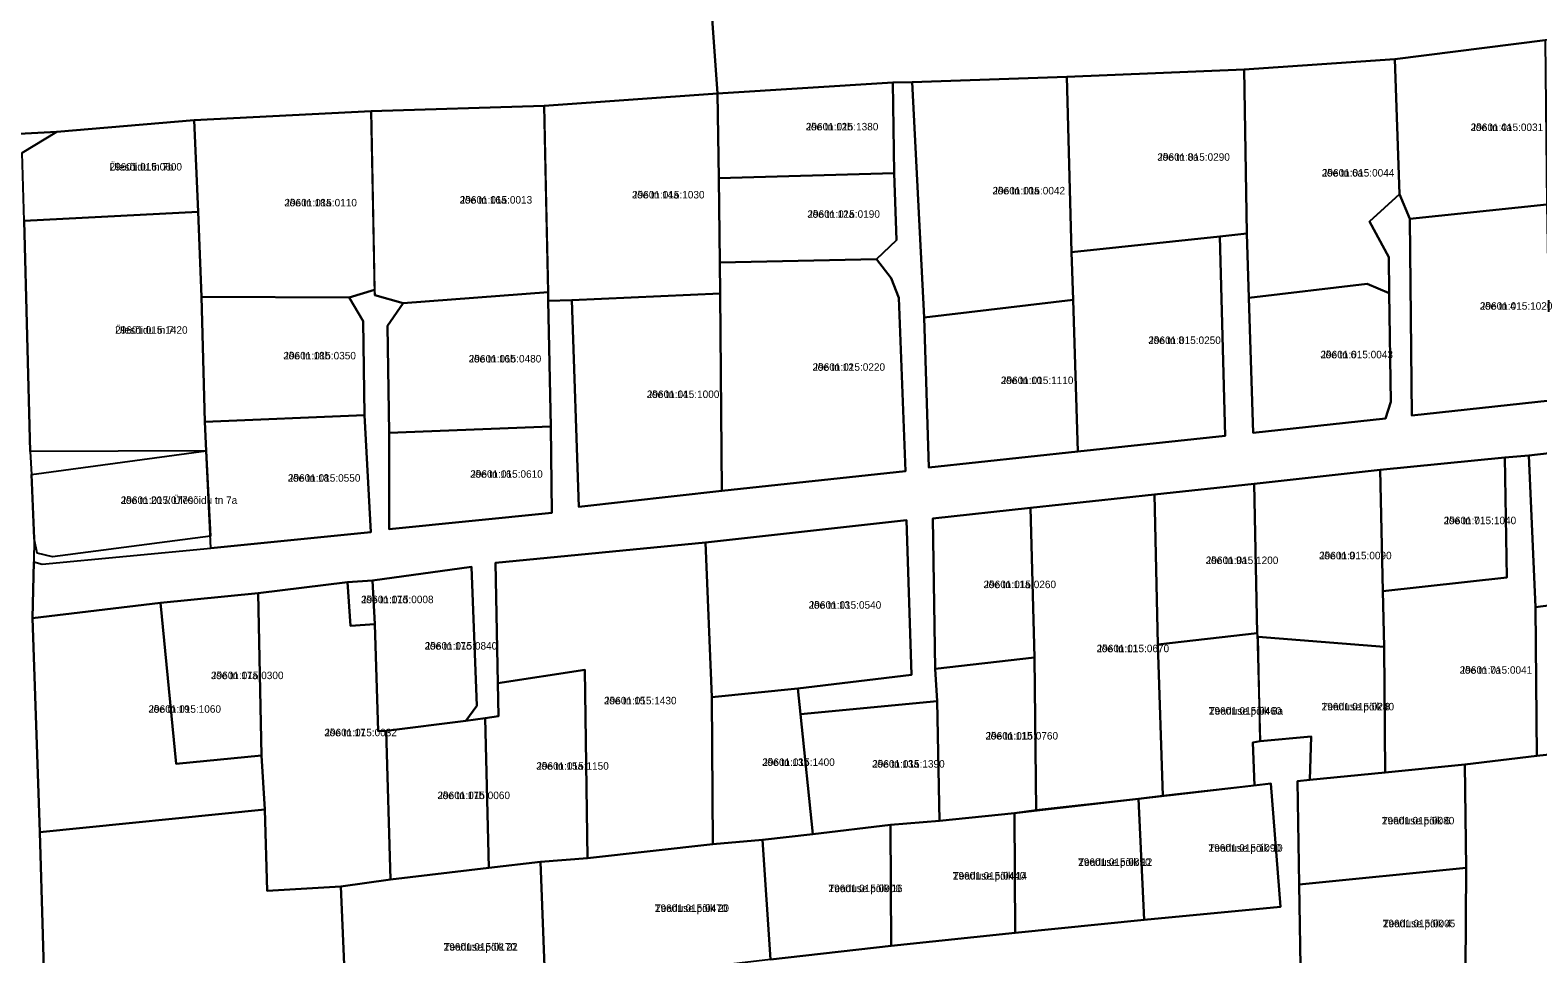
# Model space of a CAD drawing. Extents: x 518839 to 525192, y 6573164 to 6576561.
# Drawn here: x 524240.2 to 524541.9, y 6574114.7 to 6574299.5 of the extents above; entities that cross this region are included whole.
import ezdxf

# ---------------------------------------------------------------- set-up
doc = ezdxf.new("R2010")
doc.units = 0
for name, color, linetype in [('L_AADRESS', 7, 'Continuous'), ('PIIR', 7, 'Continuous'), ('TUNNUS', 7, 'Continuous')]:
    doc.layers.add(name, color=color, linetype=linetype)

msp = doc.modelspace()

# ---------------------------------------------------------------- linework, layer by layer
at = {"layer": 'PIIR'}
for points in [[(524374.42, 6574333.78), (524377.78, 6574286.88), (524343.06, 6574284.39), (524308.48, 6574283.33), (524273.05, 6574281.52), (524245.54, 6574279.22), (524236.65, 6574278.75)], [(524603.25, 6574305.18), (524560.4, 6574299.4), (524543.42, 6574297.51), (524513.3, 6574293.76), (524483.18, 6574291.7), (524447.68, 6574290.19), (524416.73, 6574289.11), (524412.88, 6574289.05), (524377.78, 6574286.88), (524374.42, 6574333.78)], [(524569.73, 6574217.81), (524540.13, 6574214.39), (524535.35, 6574214.04), (524510.4, 6574211.51), (524485.18, 6574208.72), (524465.23, 6574206.58), (524440.39, 6574203.91), (524420.86, 6574201.78), (524421.31, 6574171.7), (524421.74, 6574165.24), (524394.36, 6574162.67), (524393.82, 6574167.78), (524416.62, 6574170.5), (524415.6, 6574201.48), (524375.36, 6574196.98), (524333.35, 6574192.94), (524333.78, 6574168.84), (524333.97, 6574162.26), (524331.28, 6574161.82), (524327.38, 6574161.32), (524329.62, 6574164.28), (524328.56, 6574192.15), (524308.74, 6574189.42), (524303.69, 6574189.04), (524285.84, 6574186.87), (524266.3, 6574184.93), (524240.65, 6574181.86), (524240.91, 6574193.14), (524242.63, 6574192.69), (524276.39, 6574195.86), (524308.41, 6574199.08), (524307.1, 6574222.48), (524306.85, 6574241.32), (524304.03, 6574246.04), (524309.15, 6574247.55), (524309.17, 6574246.47), (524314.87, 6574244.93), (524311.74, 6574240.35), (524312.04, 6574218.94), (524312.08, 6574199.69), (524344.61, 6574202.92), (524344.41, 6574220.23), (524343.91, 6574245.35), (524348.63, 6574245.53), (524350.02, 6574204.11), (524378.65, 6574207.36), (524415.39, 6574211.28), (524414.07, 6574245.95), (524412.52, 6574249.93), (524409.62, 6574253.72), (524413.56, 6574257.48), (524413.15, 6574270.95), (524412.88, 6574289.05), (524416.73, 6574289.11), (524419.11, 6574242.02), (524420.07, 6574211.99), (524449.9, 6574215.23), (524479.4, 6574218.33), (524478.3, 6574258.27), (524483.73, 6574258.85), (524484.12, 6574245.98), (524484.94, 6574218.93), (524511.47, 6574221.81), (524512.54, 6574225.12), (524512.22, 6574246.88), (524512.12, 6574254.09), (524508.28, 6574261.23), (524514.29, 6574266.69), (524516.32, 6574261.81), (524516.72, 6574222.41), (524544.4, 6574225.45)], [(524236.65, 6574278.75), (524245.54, 6574279.22), (524238.6, 6574275.01)], [(524238.98, 6574261.37), (524240.23, 6574215.18), (524240.48, 6574210.62), (524241.02, 6574197.83), (524240.91, 6574193.14), (524240.65, 6574181.86), (524242.13, 6574138.99), (524243.35, 6574097.92), (524243.96, 6574077.71), (524245.35, 6574041.84), (524245.17, 6574032.64), (524245.98, 6574004.81), (524246.26, 6573990.17), (524246.35, 6573972.48), (524246.84, 6573953.26), (524247.54, 6573920.4), (524247.28, 6573908.17), (524248.4, 6573876.78), (524250.25, 6573836.78)], [(524388.38, 6574113.52), (524412.54, 6574116.25), (524437.36, 6574118.89), (524463.13, 6574121.46), (524490.46, 6574124.08), (524488.49, 6574148.75), (524485.27, 6574148.38), (524484.92, 6574156.99), (524486.37, 6574157.21), (524496.58, 6574158.19), (524496.29, 6574149.47), (524493.82, 6574149.22), (524494.16, 6574128.57), (524494.48, 6574108.1)]]:
    msp.add_lwpolyline(points, dxfattribs=at)
for points in [[(524513.3, 6574293.76), (524543.42, 6574297.51), (524543.72, 6574264.65), (524516.32, 6574261.81), (524514.29, 6574266.69)], [(524483.18, 6574291.7), (524513.3, 6574293.76), (524514.29, 6574266.69), (524508.28, 6574261.23), (524512.12, 6574254.09), (524512.22, 6574246.88), (524507.77, 6574248.8), (524484.12, 6574245.98), (524483.73, 6574258.85)], [(524416.73, 6574289.11), (524447.68, 6574290.19), (524448.61, 6574255.1), (524448.92, 6574245.6), (524419.11, 6574242.02)], [(524447.68, 6574290.19), (524483.18, 6574291.7), (524483.73, 6574258.85), (524478.3, 6574258.27), (524448.61, 6574255.1)], [(524377.78, 6574286.88), (524412.88, 6574289.05), (524413.15, 6574270.95), (524378.03, 6574269.9)], [(524343.48, 6574264.51), (524343.88, 6574247.11), (524314.87, 6574244.93), (524309.17, 6574246.47), (524308.85, 6574263.82), (524308.48, 6574283.33), (524343.06, 6574284.39)], [(524377.78, 6574286.88), (524378.03, 6574269.9), (524378.21, 6574253.02), (524378.27, 6574246.84), (524348.63, 6574245.53), (524343.91, 6574245.35), (524343.88, 6574247.11), (524343.06, 6574284.39)], [(524273.82, 6574263.18), (524238.98, 6574261.37), (524238.6, 6574275.01), (524245.54, 6574279.22), (524273.05, 6574281.52)], [(524273.82, 6574263.18), (524273.05, 6574281.52), (524308.48, 6574283.33), (524309.15, 6574247.55), (524304.03, 6574246.04), (524274.53, 6574246.16)], [(524378.03, 6574269.9), (524413.15, 6574270.95), (524413.56, 6574257.48), (524409.62, 6574253.72), (524378.21, 6574253.02)], [(524273.82, 6574263.18), (524274.53, 6574246.16), (524275.17, 6574221.13), (524275.45, 6574215.33), (524240.23, 6574215.18), (524238.98, 6574261.37)], [(524516.32, 6574261.81), (524543.72, 6574264.65), (524544.4, 6574225.45), (524516.72, 6574222.41)], [(524448.92, 6574245.6), (524448.61, 6574255.1), (524478.3, 6574258.27), (524479.4, 6574218.33), (524449.9, 6574215.23)], [(524378.27, 6574246.84), (524378.21, 6574253.02), (524409.62, 6574253.72), (524412.52, 6574249.93), (524414.07, 6574245.95), (524415.39, 6574211.28), (524378.65, 6574207.36)], [(524484.12, 6574245.98), (524507.77, 6574248.8), (524512.22, 6574246.88), (524512.54, 6574225.12), (524511.47, 6574221.81), (524484.94, 6574218.93)], [(524274.53, 6574246.16), (524304.03, 6574246.04), (524306.85, 6574241.32), (524307.1, 6574222.48), (524275.17, 6574221.13)], [(524311.74, 6574240.35), (524314.87, 6574244.93), (524343.88, 6574247.11), (524343.91, 6574245.35), (524344.41, 6574220.23), (524312.04, 6574218.94)], [(524348.63, 6574245.53), (524378.27, 6574246.84), (524378.65, 6574207.36), (524350.02, 6574204.11)], [(524419.11, 6574242.02), (524448.92, 6574245.6), (524449.9, 6574215.23), (524420.07, 6574211.99)], [(524275.45, 6574215.33), (524275.17, 6574221.13), (524307.1, 6574222.48), (524308.41, 6574199.08), (524276.39, 6574195.86)], [(524312.04, 6574218.94), (524344.41, 6574220.23), (524344.61, 6574202.92), (524312.08, 6574199.69)], [(524569.73, 6574217.81), (524569.35, 6574187.66), (524541.45, 6574184.05), (524540.13, 6574214.39)], [(524240.48, 6574210.62), (524275.45, 6574215.33), (524276.27, 6574198.28), (524244.71, 6574194.11), (524241.62, 6574194.83), (524241.02, 6574197.83)], [(524510.4, 6574211.51), (524535.35, 6574214.04), (524535.77, 6574189.99), (524510.93, 6574187.29)], [(524535.35, 6574214.04), (524540.13, 6574214.39), (524541.45, 6574184.05), (524541.71, 6574154.3), (524527.33, 6574152.59), (524511.39, 6574150.99), (524511.18, 6574176.09), (524510.93, 6574187.29), (524535.77, 6574189.99)], [(524485.18, 6574208.72), (524485.8, 6574178.88), (524465.86, 6574176.59), (524465.23, 6574206.58)], [(524485.8, 6574178.88), (524485.18, 6574208.72), (524510.4, 6574211.51), (524510.93, 6574187.29), (524511.18, 6574176.09), (524485.95, 6574178.09)], [(524466.91, 6574146.26), (524462.01, 6574145.66), (524441.53, 6574143.44), (524441.19, 6574174), (524440.39, 6574203.91), (524465.23, 6574206.58), (524465.86, 6574176.59)], [(524420.86, 6574201.78), (524440.39, 6574203.91), (524441.19, 6574174), (524421.31, 6574171.7)], [(524415.6, 6574201.48), (524416.62, 6574170.5), (524393.82, 6574167.78), (524376.6, 6574166.02), (524375.36, 6574196.98)], [(524351.2, 6574171.53), (524333.78, 6574168.84), (524333.35, 6574192.94), (524375.36, 6574196.98), (524376.6, 6574166.02), (524376.8, 6574136.64), (524351.74, 6574133.81)], [(524328.56, 6574192.15), (524329.62, 6574164.28), (524327.38, 6574161.32), (524311.47, 6574159.28), (524309.86, 6574159.26), (524309.19, 6574180.62), (524308.74, 6574189.42)], [(524285.84, 6574186.87), (524303.69, 6574189.04), (524304.33, 6574180.33), (524309.19, 6574180.62), (524309.86, 6574159.26), (524311.47, 6574159.28), (524312.35, 6574129.57), (524302.37, 6574128.15), (524287.66, 6574127.29), (524287.15, 6574143.56), (524286.53, 6574154.38)], [(524308.74, 6574189.42), (524309.19, 6574180.62), (524304.33, 6574180.33), (524303.69, 6574189.04)], [(524569.35, 6574187.66), (524571.4, 6574178.17), (524571.46, 6574157.47), (524566.75, 6574156.97), (524541.71, 6574154.3), (524541.45, 6574184.05)], [(524240.65, 6574181.86), (524266.3, 6574184.93), (524269.46, 6574152.67), (524286.53, 6574154.38), (524287.15, 6574143.56), (524242.13, 6574138.99)], [(524266.3, 6574184.93), (524285.84, 6574186.87), (524286.53, 6574154.38), (524269.46, 6574152.67)], [(524485.8, 6574178.88), (524486.37, 6574157.21), (524484.92, 6574156.99), (524485.27, 6574148.38), (524466.91, 6574146.26), (524465.86, 6574176.59)], [(524496.58, 6574158.19), (524486.37, 6574157.21), (524485.95, 6574178.09), (524511.18, 6574176.09), (524511.39, 6574150.99), (524496.29, 6574149.47)], [(524421.31, 6574171.7), (524441.19, 6574174), (524441.53, 6574143.44), (524437.19, 6574142.84), (524422.19, 6574141.31), (524421.74, 6574165.24)], [(524331.28, 6574161.82), (524333.97, 6574162.26), (524333.78, 6574168.84), (524351.2, 6574171.53), (524351.74, 6574133.81), (524342.34, 6574133.11), (524332.01, 6574131.89)], [(524376.6, 6574166.02), (524393.82, 6574167.78), (524394.36, 6574162.67), (524396.86, 6574138.64), (524386.78, 6574137.5), (524376.8, 6574136.64)], [(524394.36, 6574162.67), (524421.74, 6574165.24), (524422.19, 6574141.31), (524412.39, 6574140.52), (524396.86, 6574138.64)], [(524311.47, 6574159.28), (524327.38, 6574161.32), (524331.28, 6574161.82), (524332.01, 6574131.89), (524312.35, 6574129.57)], [(524566.74, 6574077.34), (524527.83, 6574073.06), (524527.46, 6574111.26), (524527.62, 6574131.87), (524527.33, 6574152.59), (524541.71, 6574154.3), (524566.75, 6574156.97), (524566.96, 6574123.43)], [(524493.82, 6574149.22), (524496.29, 6574149.47), (524511.39, 6574150.99), (524527.33, 6574152.59), (524527.62, 6574131.87), (524494.16, 6574128.57)], [(524462.01, 6574145.66), (524467.77, 6574146.36), (524468.4, 6574146.44), (524488.49, 6574148.75), (524490.46, 6574124.08), (524463.13, 6574121.46)], [(524437.36, 6574118.89), (524437.19, 6574142.84), (524442.86, 6574143.48), (524462.01, 6574145.66), (524463.13, 6574121.46)], [(524242.13, 6574138.99), (524287.15, 6574143.56), (524287.66, 6574127.29), (524302.37, 6574128.15), (524303.36, 6574104.74), (524303.45, 6574083.4), (524280.95, 6574080.9), (524278.06, 6574101.45), (524243.35, 6574097.92)], [(524422.19, 6574141.31), (524437.19, 6574142.84), (524437.36, 6574118.89), (524412.54, 6574116.25), (524412.39, 6574140.52)], [(524386.78, 6574137.5), (524396.86, 6574138.64), (524412.39, 6574140.52), (524412.54, 6574116.25), (524388.38, 6574113.52)], [(524343.25, 6574108.62), (524342.34, 6574133.11), (524351.74, 6574133.81), (524376.8, 6574136.64), (524386.78, 6574137.5), (524388.38, 6574113.52), (524361.28, 6574110.35)], [(524323.13, 6574106.49), (524303.36, 6574104.74), (524302.37, 6574128.15), (524312.35, 6574129.57), (524332.01, 6574131.89), (524342.34, 6574133.11), (524343.25, 6574108.62), (524343.39, 6574099.47), (524323.61, 6574097.54)], [(524527.62, 6574131.87), (524527.46, 6574111.26), (524494.48, 6574108.1), (524494.16, 6574128.57)]]:
    msp.add_lwpolyline(points, close=True, dxfattribs=at)

# ---------------------------------------------------------------- texts
at = {"layer": 'L_AADRESS'}
for s, p in [('Jõe tn 12b', (524395.46, 6574279.48)), ('Jõe tn 4a', (524528.51, 6574279.36)), ('Jõe tn 8a', (524465.81, 6574273.4)), ('Ülesõidu tn 7b', (524256.09, 6574271.45)), ('Jõe tn 6a', (524498.73, 6574270.24)), ('Jõe tn 16a', (524326.18, 6574264.83)), ('Jõe tn 14a', (524360.67, 6574265.86)), ('Jõe tn 10a', (524432.82, 6574266.67)), ('Jõe tn 18a', (524291.1, 6574264.27)), ('Jõe tn 12a', (524395.77, 6574261.99)), ('Jõe tn 4', (524530.36, 6574243.59)), ('Ülesõidu tn 7', (524257.21, 6574238.78)), ('Jõe tn 8', (524464, 6574236.73)), ('Jõe tn 18b', (524290.9, 6574233.65)), ('Jõe tn 16b', (524328, 6574233.03)), ('Jõe tn 12', (524396.8, 6574231.37)), ('Jõe tn 6', (524498.45, 6574233.87)), ('Jõe tn 10', (524434.5, 6574228.71)), ('Jõe tn 14', (524363.64, 6574225.92)), ('Jõe tn 18', (524291.8, 6574209.17)), ('Jõe tn 16', (524328.29, 6574209.96)), ('Jõe tn 20 // Ülesõidu tn 7a', (524258.34, 6574204.72)), ('Jõe tn 7', (524523.11, 6574200.66)), ('Jõe tn 9a', (524475.51, 6574192.69)), ('Jõe tn 9', (524498.18, 6574193.64)), ('Jõe tn 11a', (524431.02, 6574187.86)), ('Jõe tn 17d', (524306.44, 6574184.85)), ('Jõe tn 13', (524396.04, 6574183.75)), ('Jõe tn 17c', (524319.18, 6574175.56)), ('Jõe tn 11', (524453.65, 6574175.04)), ('Jõe tn 17a', (524276.41, 6574169.65)), ('Jõe tn 7a', (524526.32, 6574170.73)), ('Jõe tn 19', (524263.9, 6574162.92)), ('Jõe tn 15', (524355.07, 6574164.61)), ('Teaduse põik 8a', (524476.11, 6574162.55)), ('Teaduse põik 8', (524498.67, 6574163.4)), ('Jõe tn 17', (524299.1, 6574158.22)), ('Jõe tn 11b', (524431.42, 6574157.56)), ('Jõe tn 15a', (524341.51, 6574151.52)), ('Jõe tn 13b', (524386.73, 6574152.28)), ('Jõe tn 13a', (524408.73, 6574151.94)), ('Jõe tn 17b', (524321.74, 6574145.64)), ('Teaduse põik 6', (524510.73, 6574140.58)), ('Teaduse põik 10', (524476.04, 6574135.11)), ('Teaduse põik 12', (524449.95, 6574132.28)), ('Teaduse põik 14', (524424.87, 6574129.54)), ('Teaduse põik 16', (524399.98, 6574127.02)), ('Teaduse põik 20', (524365.23, 6574123.06)), ('Teaduse põik 4', (524510.91, 6574119.99)), ('Teaduse põik 22', (524322.96, 6574115.32))]:
    msp.add_text(s, height=1.5, dxfattribs=at).set_placement(p)
at = {"layer": 'TUNNUS'}
for s, p in [('29601:015:1380', (524395.46, 6574279.48)), ('29601:015:0031', (524528.51, 6574279.36)), ('29601:015:0290', (524465.81, 6574273.4)), ('29601:015:0600', (524256.09, 6574271.45)), ('29601:015:0044', (524498.73, 6574270.24)), ('29601:015:0013', (524326.18, 6574264.83)), ('29601:015:1030', (524360.67, 6574265.86)), ('29601:015:0042', (524432.82, 6574266.67)), ('29601:015:0110', (524291.1, 6574264.27)), ('29601:015:0190', (524395.77, 6574261.99)), ('29601:015:1020', (524530.36, 6574243.59)), ('29601:015:1420', (524257.21, 6574238.78)), ('29601:015:0250', (524464, 6574236.73)), ('29601:015:0350', (524290.9, 6574233.65)), ('29601:015:0480', (524328, 6574233.03)), ('29601:015:0220', (524396.8, 6574231.37)), ('29601:015:0043', (524498.45, 6574233.87)), ('29601:015:1110', (524434.5, 6574228.71)), ('29601:015:1000', (524363.64, 6574225.92)), ('29601:015:0550', (524291.8, 6574209.17)), ('29601:015:0610', (524328.29, 6574209.96)), ('29601:015:0770', (524258.34, 6574204.72)), ('29601:015:1040', (524523.11, 6574200.66)), ('29601:015:1200', (524475.51, 6574192.69)), ('29601:015:0090', (524498.18, 6574193.64)), ('29601:015:0260', (524431.02, 6574187.86)), ('29601:015:0008', (524306.44, 6574184.85)), ('29601:015:0540', (524396.04, 6574183.75)), ('29601:015:0840', (524319.18, 6574175.56)), ('29601:015:0670', (524453.65, 6574175.04)), ('29601:015:0300', (524276.41, 6574169.65)), ('29601:015:0041', (524526.32, 6574170.73)), ('29601:015:1060', (524263.9, 6574162.92)), ('29601:015:1430', (524355.07, 6574164.61)), ('29601:015:0460', (524476.11, 6574162.55)), ('29601:015:0240', (524498.67, 6574163.4)), ('29601:015:0032', (524299.1, 6574158.22)), ('29601:015:0760', (524431.42, 6574157.56)), ('29601:015:1150', (524341.51, 6574151.52)), ('29601:015:1400', (524386.73, 6574152.28)), ('29601:015:1390', (524408.73, 6574151.94)), ('29601:015:0060', (524321.74, 6574145.64)), ('29601:015:0080', (524510.73, 6574140.58)), ('29601:015:1090', (524476.04, 6574135.11)), ('29601:015:0890', (524449.95, 6574132.28)), ('29601:015:0440', (524424.87, 6574129.54)), ('29601:015:0900', (524399.98, 6574127.02)), ('29601:015:0470', (524365.23, 6574123.06)), ('29601:015:0005', (524510.91, 6574119.99)), ('29601:015:0170', (524322.96, 6574115.32))]:
    msp.add_text(s, height=1.5, dxfattribs=at).set_placement(p)

doc.saveas('drawing.dxf')
